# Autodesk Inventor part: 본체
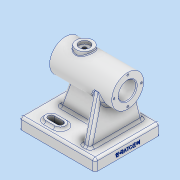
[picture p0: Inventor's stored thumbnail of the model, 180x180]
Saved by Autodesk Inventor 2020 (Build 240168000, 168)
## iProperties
Created: 2021-11
Part Number: 본체
Material: 알루미늄 6061
Document SubType Name: Modeling
Designer: user
Density: 2.7 g/cm^3
Appearance: 알루미늄 - 평지
Mass: 632.893 g
Surface Area: 512.994 cm^2
Volume: 234.405 cm^3
Author: user
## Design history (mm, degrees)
sketch "스케치1"
  geometry: L1 (43, -50)-(-43, -50); L2 (-43, -50)-(-43, 50); L3 (-43, 50)-(43, 50); L4 (43, 50)-(43, -50); L5 (43, -50)-(-43, 50); L6 (-43, -50)-(43, 50); 1 further point
  constraints: 12 end point, 2 midpoint, 2 parallel, 1 horizontal, 1 perpendicular
  dimensions: "d0" = 100 distance of L3.end L1.start; "d1" = 86 distance of L1.start L1.end
extrude "돌출1" new body sketch "스케치1" distance "d2" = 15; taper "d3" = 0 deg
sketch "스케치2"
  geometry: L1 (-27, -24)-(-27, -12); L2 (-20, -24)-(-20, -12); L3 (-34, -12)-(-34, -24); L4 (-43, 50)-(-43, -50) reference; L5 (-43, -50)-(43, -50) reference; A1 r 7 centre (-27, -24) between (-34, -24) and (-20, -24); A2 r 7 centre (-27, -12) between (-20, -12) and (-34, -12); 2 further points
  constraints: 8 end point, 4 point on circle, 4 tangent, 2 centre point, 1 midpoint, 1 parallel, 1 vertical
  dimensions: "d4" = 12 distance of L1.end L1.start; "d5" = 16 distance from line of L1.start L4; "d6" = 26 distance from line of L5 L1.start; "d7" = 14 distance between parallel lines of L2 L3
extrude "돌출2" join sketch "스케치2" distance "d8" = 3; taper "d9" = 0 deg
sketch "스케치3"
  geometry: L1 (-27, -24)-(-27, -12); L2 (-31, -24)-(-31, -12); L3 (-23, -12)-(-23, -24); A1 r 7 centre (-27, -24) between (-34, -24) and (-20, -24) reference; A2 r 7 centre (-27, -12) between (-20, -12) and (-34, -12) reference; A3 r 4 centre (-27, -24) between (-31, -24) and (-23, -24); A4 r 4 centre (-27, -12) between (-23, -12) and (-31, -12); 2 further points
  constraints: 8 end point, 4 point on circle, 4 tangent, 2 centre point, 1 midpoint, 1 parallel, 1 vertical
  dimensions: "d10" = 8 distance between parallel lines of L3 L2
extrude "돌출3" cut sketch "스케치3" stored distance "d11" = 3; taper "d12" = 0 deg
sketch "스케치4"
  geometry: L1 (0, 0)-(86, 0) reference; C1 r 21 at (43, 72); 2 further points
  constraints: 1 centre point, 1 midpoint, 1 vertical alignment
  dimensions: "d13" = 42 diameter of C1; "d14" = 72 distance of point (43, 0) C1.centre
extrude "돌출4" join sketch "스케치4" distance "d15" = 82; taper "d16" = 0 deg
sketch "스케치5"
  geometry: C1 r 11.5 at (0, 0); C2 r 21 at (0, 0) reference; 1 further point
  constraints: 1 centre point, 1 concentric
  dimensions: "d17" = 23 diameter of C1
extrude "돌출5" cut sketch "스케치5" stored distance "d18" = 82; taper "d19" = 0 deg
sketch "스케치6"
  geometry: C1 r 14.5 at (0, 0); C2 r 21 at (0, 0) reference; 1 further point
  constraints: 1 centre point, 1 concentric
  dimensions: "d20" = 29 diameter of C1
extrude "돌출6" cut sketch "스케치6" distance "d21" = 62; taper "d22" = 0 deg
sketch "스케치7"
  geometry: C1 r 21 at (0, 0) reference; 2 further points
  constraints: 1 vertical alignment
  dimensions: "d23" = 18 distance of C1.centre point (0, 18)
hole "구멍1" sketch "스케치7" at (0, 18) diameter "d24" = 2.459; stored, may be unused: countersink angle "d28" = 90 deg, drill point angle "d30" = 118 deg; dims "d25" = 8, "d26" = 4, "d27" = 2, "d29" = 10
sketch "스케치8"
  geometry: C1 r 21 at (0, 0) reference; 2 further points
  constraints: 1 vertical alignment
  dimensions: "d34" = 18 distance of point (0, 18) C1.centre
hole "구멍2" sketch "스케치8" at (0, 18) diameter "d35" = 2.459; stored, may be unused: countersink angle "d39" = 90 deg, drill point angle "d41" = 118 deg; dims "d36" = 8, "d37" = 4, "d38" = 2, "d40" = 10
node "작업 평면1"
sketch "스케치9"
  geometry: L1 (21, 72)-(35, 15); L2 (-43, 15)-(43, 15) reference; L3 (35, 15)-(-35, 15); L4 (-35, 15)-(-21, 72); L5 (-43, 0)-(-43, 15) reference; L6 (43, 0)-(43, 15) reference; A1 r 21 centre (0, 72) between (-21, 72) and (21, 72); 5 further points
  constraints: 6 end point, 2 coincident, 2 point on circle, 1 centre point, 1 horizontal, 1 point on line, 2 other
  dimensions: "d46" = 8 distance from line of L5 L3.end; "d47" = 8 distance from line of L6 L1.end; "d48" = 57 vertical distance of L1.start L1.end; "d49" = 57 vertical distance of L3.end L4.end
extrude "돌출7" join sketch "스케치9" distance "d50" = 10; taper "d51" = 0 deg
node "작업 평면2"
fillet "모깎기2" dims "d69" = 3
fillet "모깎기3" dims "d70" = 3
fillet "모깎기4" dims "d71" = 3
fillet "모깎기5" dims "d72" = 3
sketch "스케치13"
  geometry: L1 (21, 32)-(-21, 32) reference; C1 r 11 at (0, 7); 1 further point
  constraints: 1 centre point
  dimensions: "d78" = 22 diameter of C1; "d79" = 25 distance from line of L1 C1.centre
extrude "돌출10" join sketch "스케치13" stored distance "d80" = 10; taper "d81" = 0 deg
sketch "스케치14"
  geometry: L1 (15, 35)-(51, 21.897); L2 (54, -39.261)-(52.77, -40) reference; L3 (52.77, -40)-(52.77, -50) reference; L4 (52.77, -50)-(51, -50) reference; L5 (51, -50)-(51, -35) reference; L6 (51, -35)-(15, -35) reference; L7 (15, -35)-(15, -47) reference; L8 (12, -50)-(0, -50) reference; L9 (0, -50)-(0, 50) reference; L10 (0, 50)-(12, 50) reference; L11 (15, 47)-(15, -25) reference; L12 (15, -25)-(51, -25) reference; L13 (51, -25)-(51, 32) reference; L14 (51, 32)-(52.771, 32) reference; L15 (52.771, 32)-(52.771, 22) reference; L16 (52.771, 22)-(54, 21.261) reference; L17 (54, 21.261)-(55.23, 22) reference; L18 (55.23, 22)-(55.23, 32) reference; L19 (55.23, 32)-(57.5, 32) reference; L20 (57.5, 32)-(57.5, -30) reference; L21 (57.5, -30)-(60.5, -30) reference; L22 (60.5, -30)-(60.5, -50) reference; L23 (60.5, -50)-(55.23, -50) reference; L24 (55.23, -50)-(55.23, -40) reference; L25 (55.23, -40)-(54, -39.261) reference; L26 (91.23, -40)-(90, -39.261) reference; L27 (90, -39.261)-(88.77, -40) reference; L28 (88.77, -40)-(88.77, -50) reference; L29 (88.77, -50)-(83.5, -50) reference; L30 (83.5, -50)-(83.5, -30) reference; L31 (83.5, -30)-(86.5, -30) reference; L32 (86.5, -30)-(86.5, 32) reference; L33 (86.5, 32)-(88.77, 32) reference; L34 (88.77, 32)-(88.77, 22) reference; L35 (88.77, 22)-(90, 21.261) reference; L36 (90, 21.261)-(91.23, 22) reference; L37 (91.23, 22)-(91.23, 32) reference; L38 (91.23, 32)-(93, 32) reference; L39 (93, 32)-(93, 18) reference; L40 (93, 18)-(96, 18) reference; L41 (96, 18)-(96, -4) reference; L42 (96, -4)-(93, -4) reference; L43 (93, -4)-(93, -50) reference; L44 (93, -50)-(91.23, -50) reference; L45 (91.23, -50)-(91.23, -40) reference; A1 r 3 centre (12, -47) between (12, -50) and (15, -47) reference; A2 r 3 centre (12, 47) between (15, 47) and (12, 50) reference; 1 further point
  constraints: 2 end point, 2 point on line
  dimensions: "d83" = 15 distance from line of L10 L1.start; "d84" = 70 deg angle of L11 L1
feature "리브1" sketch "스케치14" dims "d85" = 1, "d86" = 10, "d87" = 0, "d88" = 0, "d89" = 1, "d90" = 1
fillet "모깎기7" dims "d91" = 3
fillet "모깎기8" dims "d92" = 3
fillet "모깎기9" dims "d93" = 3
sketch "스케치15"
  geometry: C1 r 11 at (0, 0) reference; 2 further points
  constraints: 1 coincident
hole "구멍4" sketch "스케치15" at (0, 0) diameter "d94" = 4.917; stored, may be unused: countersink angle "d98" = 90 deg, drill point angle "d100" = 118 deg; dims "d95" = 12, "d96" = 14, "d97" = 4, "d99" = 8
fillet "모깎기10" dims "d101" = 1
chamfer "모따기1" distance "d102" = 1; stored, may be unused: second distance "d103" = 2, angle "d104" = 45 deg
sketch "스케치16"
  geometry: L1 (0, 0)-(80, 0) reference; 3 further points
  constraints: 1 midpoint, 1 vertical alignment, 1 other
  dimensions: "d105" = 6 distance from line of L1 point (40, 6)
feature "엠보싱1" sketch "스케치16" dims "d0" = 100, "d1" = 86, "d106" = 0.5, "d107" = 0
node "솔리드1"
mirror "미러1"
mirror "미러2"
pattern_circular "원형 패턴1" dims angle "d32" = 360 deg
pattern_circular "원형 패턴2" dims angle "d43" = 360 deg
node "절단 모서리 투영1"
feature "A9D066F2-1C7D-4E18-AEED-F7BC21143FA4" dims "d24" = 2.459, "d25" = 8, "d26" = 4, "d27" = 2, "d28" = 90 deg, "d29" = 10, "d30" = 118 deg
other parameters: "d45" = -35, "d56" = 96
